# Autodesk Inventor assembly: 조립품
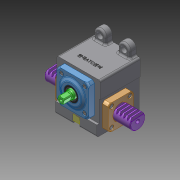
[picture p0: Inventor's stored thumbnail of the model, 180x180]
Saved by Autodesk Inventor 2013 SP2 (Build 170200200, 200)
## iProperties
Created: 2024-11
Part Number: 조립품
Document SubType Name: Assembly
Designer: a
Author: a
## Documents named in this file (10)
- C:\Users\a\Desktop\741104V1017\조립품.iam
- C:\Users\a\Desktop\741104V1017\본체.ipt
- C:\Users\a\Desktop\741104V1017\깊음 홈 볼 베어링 6202.ipt
- C:\Users\a\Desktop\741104V1017\피니언 축.ipt
- C:\Users\a\Desktop\741104V1017\커버.ipt
- C:\Users\a\Desktop\741104V1017\오일 실 15 25 4.ipt
- C:\Users\a\Desktop\741104V1017\수지 부시.ipt
- C:\Users\a\Desktop\741104V1017\육각 소켓 머리 볼트 M4x10.ipt
- C:\Users\a\Desktop\741104V1017\스톱퍼.ipt
- C:\Users\a\Desktop\741104V1017\래크.ipt
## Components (1 placed, 1 different names)
1. 피니언 축:1
